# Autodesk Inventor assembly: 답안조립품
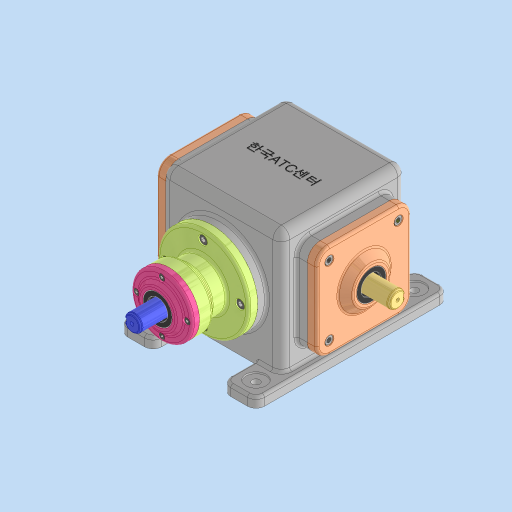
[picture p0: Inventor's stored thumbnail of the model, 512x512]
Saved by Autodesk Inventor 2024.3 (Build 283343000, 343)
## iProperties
Created: 2026-01
Part Number: 답안조립품
Document SubType Name: Assembly
Designer: PC2-02
Author: PC2-02
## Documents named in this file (16)
- C:\Users\PC2-02\Desktop\760103V1006\답안조립품.iam
- C:\Users\PC2-02\Desktop\760103V1006\본체.ipt
- C:\Users\PC2-02\Desktop\760103V1006\종동축\종동축.ipt
- C:\Users\PC2-02\Desktop\760103V1006\측면 커버\측면 커버.ipt
- C:\Users\PC2-02\Desktop\760103V1006\오일 실 20 35 8\오일 실 20 35 8.ipt
- C:\Users\PC2-02\Desktop\760103V1006\테이퍼 롤러 베어링 30204K\테이퍼 롤러 베어링 30204K.ipt
- C:\Users\PC2-02\Desktop\760103V1006\칼라\칼라.ipt
- C:\Users\PC2-02\Desktop\760103V1006\평행 키 6x6x18\평행 키 6x6x18.ipt
- C:\Users\PC2-02\Desktop\760103V1006\베벨 기어(종동)\베벨 기어(종동).ipt
- C:\Users\PC2-02\Desktop\760103V1006\구동축\구동축.ipt
- C:\Users\PC2-02\Desktop\760103V1006\베어링 하우징\베어링 하우징.ipt
- C:\Users\PC2-02\Desktop\760103V1006\베벨 기어(구동)\베벨 기어(구동).ipt
- C:\Users\PC2-02\Desktop\760103V1006\엔드캡\엔드캡.ipt
- C:\Users\PC2-02\Desktop\760103V1006\6각 구멍붙이 볼트 M6x12\6각 구멍붙이 볼트 M6x12.ipt
- C:\Users\PC2-02\Desktop\760103V1006\하우징 커버\하우징 커버.ipt
- C:\Users\PC2-02\Desktop\760103V1006\6각 구멍붙이 볼트 M4x10\6각 구멍붙이 볼트 M4x10.ipt
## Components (19 placed, 4 different names)
1. 구동축:1
2. 6각 구멍붙이 볼트 M6x12:1
3. 6각 구멍붙이 볼트 M6x12:2
4. 6각 구멍붙이 볼트 M6x12:3
5. 6각 구멍붙이 볼트 M6x12:4
6. 하우징 커버:1
7. 6각 구멍붙이 볼트 M4x10:1
8. 6각 구멍붙이 볼트 M4x10:2
9. 6각 구멍붙이 볼트 M4x10:3
10. 6각 구멍붙이 볼트 M4x10:4
11. 6각 구멍붙이 볼트 M6x12:5
12. 6각 구멍붙이 볼트 M6x12:7
13. 6각 구멍붙이 볼트 M6x12:8
14. 6각 구멍붙이 볼트 M6x12:9
15. 6각 구멍붙이 볼트 M6x12:13
16. 6각 구멍붙이 볼트 M6x12:6
17. 6각 구멍붙이 볼트 M6x12:10
18. 6각 구멍붙이 볼트 M6x12:11
19. 6각 구멍붙이 볼트 M6x12:12
